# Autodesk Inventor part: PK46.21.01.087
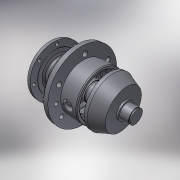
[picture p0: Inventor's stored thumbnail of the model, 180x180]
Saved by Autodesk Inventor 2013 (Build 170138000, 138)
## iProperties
Created: 2005-03
Part Number: PK46.21.01.087
Material: Steel, Mild
Document SubType Name: Modeling
Designer: salex
Manufacturer: Standard
Standards Organization: Custom
Density: 7.86 g/cm^3
Mass: 19576 g
Surface Area: 3298.53 cm^2
Volume: 2490.58 cm^3
Author: salex
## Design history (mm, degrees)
feature "Sculpt1"
body "Solid2"
feature "Surface1"
body "Srf1"
